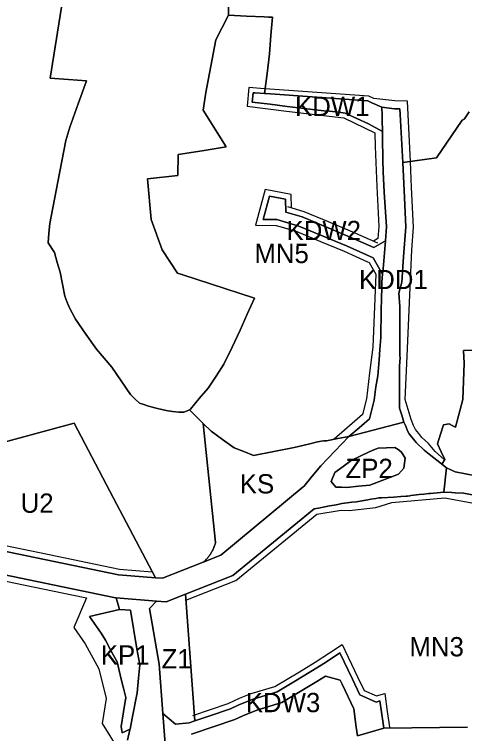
# Model space of a CAD drawing. Extents: x 7439486 to 7443435, y 5551288 to 5554556.
# Drawn here: x 7441851.7 to 7442085.2, y 5553243.9 to 5553616.6 of the extents above; entities that cross this region are included whole.
import ezdxf

# ---------------------------------------------------------------- set-up
doc = ezdxf.new("R2010")
doc.units = 0
for name, color, linetype in [('linie_rozgraniczajace', 7, 'Continuous'), ('linie_zabudowy_nieprzekraczalne', 7, 'Continuous'), ('oznaczenia_przeznaczen', 7, 'Continuous')]:
    doc.layers.add(name, color=color, linetype=linetype)

msp = doc.modelspace()

# ---------------------------------------------------------------- linework, layer by layer
at = {"layer": 'linie_rozgraniczajace'}
for points in [[(7441962.75, 5553632.44), (7441962.74, 5553616.11), (7441959.49, 5553609.73), (7441956.24, 5553603.34), (7441950.99, 5553576.02), (7441949.63, 5553566.86), (7441961.61, 5553547.92), (7441949.1, 5553545.9), (7441936.59, 5553543.88), (7441936.53, 5553533.08), (7441920.77, 5553531.3), (7441922.7, 5553510.32), (7441928.27, 5553494.51), (7441936.24, 5553482.52), (7441938.5, 5553481.78), (7441976.24, 5553469.44), (7441972.5, 5553461.19), (7441968.76, 5553452.94), (7441964.58, 5553444.11), (7441960.4, 5553435.27), (7441956.27, 5553429.09), (7441952.13, 5553422.91), (7441947.59, 5553417.49), (7441943.06, 5553412.07), (7441942.78, 5553411.84), (7441942.49, 5553411.61), (7441941, 5553411.04), (7441939.51, 5553410.48), (7441938.2, 5553410.46), (7441936.89, 5553410.43), (7441933.65, 5553410.86), (7441930.41, 5553411.3), (7441925.85, 5553412.42), (7441921.3, 5553413.55), (7441918.9, 5553414.35), (7441916.5, 5553415.15), (7441914.23, 5553417.4), (7441911.97, 5553419.64), (7441907.06, 5553426.72), (7441902.15, 5553433.79), (7441898.19, 5553438.45), (7441894.23, 5553443.11), (7441888.76, 5553450.84), (7441883.29, 5553458.57)], [(7442087.62, 5553566.03), (7442085.21, 5553562.48), (7442084.62, 5553562.08), (7442084.03, 5553561.67), (7442070.63, 5553542.14), (7442053.16, 5553539.76), (7442051.83, 5553564.65), (7442051.71, 5553567.66), (7442048.83, 5553567.69), (7442042.23, 5553568.53), (7442037.14, 5553570.76), (7442035.02, 5553571.68), (7441982.1, 5553575.51), (7441981.44, 5553575.5), (7441982.72, 5553585.84), (7441984, 5553596.18), (7441984.78, 5553605.62), (7441985.56, 5553615.05), (7441983.44, 5553615.15), (7441981.32, 5553615.25), (7441972.03, 5553615.68), (7441962.74, 5553616.11), (7441962.75, 5553632.44)], [(7441883.29, 5553458.57), (7441880.04, 5553464.85), (7441878.91, 5553467.7), (7441877.78, 5553470.56), (7441876.61, 5553476.73), (7441875.44, 5553482.9), (7441873.94, 5553488), (7441872.43, 5553493.11), (7441869.15, 5553498.19), (7441869.56, 5553503.21), (7441869.97, 5553508.24), (7441874.19, 5553529.73), (7441878.41, 5553551.23), (7441880.51, 5553558.15), (7441884.77, 5553570.17), (7441889.02, 5553582.18), (7441879.67, 5553582.82), (7441870.31, 5553583.46), (7441877.29, 5553628.08)], [(7441877.29, 5553628.08), (7441870.31, 5553583.46), (7441879.67, 5553582.82), (7441889.02, 5553582.18), (7441884.77, 5553570.17), (7441880.51, 5553558.15), (7441878.41, 5553551.23), (7441874.19, 5553529.73), (7441869.97, 5553508.24), (7441869.56, 5553503.21), (7441869.15, 5553498.19), (7441872.43, 5553493.11), (7441873.94, 5553488), (7441875.44, 5553482.9), (7441876.61, 5553476.73), (7441877.78, 5553470.56), (7441878.91, 5553467.7), (7441880.04, 5553464.85), (7441883.29, 5553458.57), (7441888.76, 5553450.84), (7441894.23, 5553443.11), (7441898.19, 5553438.45), (7441902.15, 5553433.79), (7441907.06, 5553426.72), (7441911.97, 5553419.64), (7441914.23, 5553417.4), (7441916.5, 5553415.15), (7441918.9, 5553414.35), (7441921.3, 5553413.55), (7441925.85, 5553412.42), (7441930.41, 5553411.3), (7441933.65, 5553410.86), (7441936.89, 5553410.43), (7441938.2, 5553410.46), (7441939.51, 5553410.48), (7441941, 5553411.04), (7441942.49, 5553411.61), (7441948.12, 5553406.08), (7441949.66, 5553404.57), (7441956, 5553342.87), (7441955.99, 5553342.81), (7441955.92, 5553342.54), (7441955.84, 5553342.27), (7441955.76, 5553342), (7441955.67, 5553341.73), (7441955.58, 5553341.46), (7441955.49, 5553341.19), (7441955.39, 5553340.93), (7441955.29, 5553340.66), (7441955.19, 5553340.4), (7441955.08, 5553340.14), (7441954.97, 5553339.88), (7441954.86, 5553339.62), (7441954.74, 5553339.36), (7441954.61, 5553339.11), (7441954.49, 5553338.85), (7441954.36, 5553338.6), (7441954.23, 5553338.35), (7441954.09, 5553338.1), (7441953.95, 5553337.86), (7441953.81, 5553337.61), (7441953.66, 5553337.37), (7441953.51, 5553337.13), (7441953.36, 5553336.9), (7441953.2, 5553336.66), (7441953.04, 5553336.43), (7441952.88, 5553336.2), (7441952.71, 5553335.97), (7441952.54, 5553335.74), (7441952.37, 5553335.52), (7441952.19, 5553335.3), (7441952.01, 5553335.08), (7441951.83, 5553334.86), (7441951.64, 5553334.65), (7441951.45, 5553334.44), (7441951.26, 5553334.23), (7441951.07, 5553334.03), (7441950.87, 5553333.82), (7441950.67, 5553333.62), (7441950.47, 5553333.43)], [(7441950.47, 5553333.43), (7441950.26, 5553333.23), (7441950.05, 5553333.04), (7441949.84, 5553332.85), (7441949.63, 5553332.67), (7441928.52, 5553324.38), (7441924.88, 5553324.65), (7441903.12, 5553365.93), (7441882.64, 5553404.78), (7441837.94, 5553392.64), (7441797.85, 5553381.74), (7441779.89, 5553399.7), (7441772.37, 5553423.56), (7441763.1, 5553465.1), (7441762.38, 5553469.23), (7441761.15, 5553476.2), (7441760.08, 5553479.21), (7441754.84, 5553512.36), (7441748.26, 5553539.53), (7441742.45, 5553554.52), (7441720.8, 5553590.65), (7441712.24, 5553615.6)], [(7442095.79, 5553442.72), (7442084.64, 5553442.43), (7442084.84, 5553439.13), (7442085.04, 5553435.82), (7442084.71, 5553426.45), (7442084.38, 5553417.07), (7442082.73, 5553411.05), (7442080.55, 5553402.75), (7442078.85, 5553403.53), (7442077.15, 5553404.32), (7442074.34, 5553403.88), (7442072.78, 5553398.98), (7442071.22, 5553394.08), (7442073.09, 5553389.97), (7442074.96, 5553385.86), (7442073.48, 5553383.49), (7442072.38, 5553384.39), (7442067.78, 5553387.97), (7442064.3, 5553390.67), (7442060.1, 5553394.64), (7442056.47, 5553399.26), (7442055.81, 5553400.37), (7442054.5, 5553403.48), (7442053.72, 5553405.32), (7442052.62, 5553408.93), (7442051.52, 5553412.54), (7442051.5, 5553415.07), (7442051.48, 5553417.6), (7442051.5, 5553425.9), (7442051.5, 5553429.07), (7442051.51, 5553434.19), (7442051.63, 5553436.52), (7442051.76, 5553438.85), (7442051.7, 5553439.45), (7442051.64, 5553465.17), (7442051.06, 5553472.18), (7442052.63, 5553477.77), (7442053.53, 5553490.87), (7442054.72, 5553506.39), (7442053.93, 5553525.25), (7442053.16, 5553539.76), (7442070.63, 5553542.14), (7442084.03, 5553561.67), (7442084.62, 5553562.08), (7442085.21, 5553562.48), (7442087.62, 5553566.03)], [(7442082.73, 5553411.05), (7442084.38, 5553417.07), (7442084.71, 5553426.45), (7442085.04, 5553435.82), (7442084.84, 5553439.13), (7442084.64, 5553442.43), (7442095.79, 5553442.72)], [(7442112.53, 5553373.36), (7442080.38, 5553379.45), (7442075.77, 5553381.65), (7442073.48, 5553383.49), (7442074.96, 5553385.86), (7442073.09, 5553389.97), (7442071.22, 5553394.08), (7442072.78, 5553398.98), (7442074.34, 5553403.88), (7442077.15, 5553404.32), (7442078.85, 5553403.53), (7442080.55, 5553402.75), (7442082.73, 5553411.05)], [(7441824.52, 5553342.9), (7441905.74, 5553326.1), (7441924.88, 5553324.65), (7441928.52, 5553324.38), (7441949.63, 5553332.67), (7441958.83, 5553336.28), (7442001.52, 5553371.75), (7442001.79, 5553371.99), (7442006.18, 5553377.33), (7442010.57, 5553382.67), (7442017.91, 5553390.22), (7442025.24, 5553397.77), (7442053.72, 5553405.32), (7442054.5, 5553403.48), (7442055.81, 5553400.37), (7442056.47, 5553399.26), (7442060.1, 5553394.64), (7442064.3, 5553390.67), (7442067.78, 5553387.97), (7442072.38, 5553384.39), (7442073.48, 5553383.49), (7442075.77, 5553381.65), (7442074.52, 5553369.06), (7442067.61, 5553368.34), (7442066.62, 5553368.23), (7442064.13, 5553367.97), (7442061.65, 5553367.71), (7442058.83, 5553367.42), (7442057.26, 5553367.2), (7442056.85, 5553367.14), (7442055.69, 5553366.98), (7442054.87, 5553366.87), (7442052.2, 5553366.7), (7442048.46, 5553366.47), (7442042.04, 5553366.06), (7442040.73, 5553366.03), (7442039.25, 5553365.77), (7442036.6, 5553365.3), (7442034.97, 5553365.01), (7442030.05, 5553364.13), (7442029.21, 5553363.98), (7442026.77, 5553363.73), (7442024.33, 5553363.49), (7442022.97, 5553363.26), (7442021.61, 5553363.03), (7442020.11, 5553362.75), (7442018.61, 5553362.47), (7442017.62, 5553362.28), (7442015.17, 5553361.82), (7442012.71, 5553361.36), (7442009.38, 5553360.73), (7442007.23, 5553360.33), (7441964.97, 5553325.8), (7441940.46, 5553316.18), (7441930.35, 5553312.2), (7441925.47, 5553312.57), (7441904.54, 5553314.16), (7441904.06, 5553314.19), (7441823.17, 5553330.92)], [(7442074.52, 5553369.06), (7442075.77, 5553381.65), (7442080.38, 5553379.45), (7442112.53, 5553373.36)], [(7442086.81, 5553247.26), (7442043.26, 5553246.77), (7442042.92, 5553249.2), (7442041.28, 5553260.8), (7442039.37, 5553260.22), (7442030.91, 5553263.95), (7442027.04, 5553272.06), (7442020.54, 5553285.65), (7442013.02, 5553280.81), (7442005.49, 5553275.98), (7441996.71, 5553270.74), (7441987.93, 5553265.51), (7441981.71, 5553263.64), (7441975.49, 5553261.76), (7441971.59, 5553260.19), (7441967.69, 5553258.62), (7441963.71, 5553256.74), (7441953.02, 5553253.12), (7441945.2, 5553250.47), (7441940.46, 5553316.18), (7441964.97, 5553325.8), (7442007.23, 5553360.33), (7442009.38, 5553360.73), (7442012.71, 5553361.36), (7442015.17, 5553361.82), (7442017.62, 5553362.28), (7442018.61, 5553362.47), (7442020.11, 5553362.75), (7442021.61, 5553363.03), (7442022.97, 5553363.26), (7442024.33, 5553363.49), (7442026.77, 5553363.73), (7442029.21, 5553363.98), (7442030.05, 5553364.13), (7442034.97, 5553365.01), (7442036.6, 5553365.3), (7442039.25, 5553365.77), (7442040.73, 5553366.03), (7442042.04, 5553366.06), (7442048.46, 5553366.47), (7442052.2, 5553366.7), (7442054.87, 5553366.87), (7442055.69, 5553366.98), (7442056.85, 5553367.14), (7442057.26, 5553367.2), (7442058.83, 5553367.42), (7442061.65, 5553367.71), (7442064.13, 5553367.97), (7442066.62, 5553368.23), (7442067.61, 5553368.34), (7442074.52, 5553369.06), (7442078.57, 5553368.82), (7442080.26, 5553368.71), (7442084.74, 5553368.45), (7442109.65, 5553363.73)], [(7442109.65, 5553363.73), (7442084.74, 5553368.45), (7442080.26, 5553368.71), (7442078.57, 5553368.82), (7442074.52, 5553369.06)], [(7441625.43, 5553307.24), (7441692.79, 5553320.41), (7441753.67, 5553331.12), (7441780.26, 5553331.8), (7441823.17, 5553330.92), (7441904.06, 5553314.19), (7441904.54, 5553314.16), (7441906.16, 5553308.16), (7441890.69, 5553304.55), (7441896.75, 5553295.85), (7441898.88, 5553292.27), (7441901.92, 5553286.67), (7441904.97, 5553281.08), (7441907.04, 5553272.17), (7441908.22, 5553267.37), (7441909.4, 5553262.57), (7441908.24, 5553255.09), (7441907.09, 5553247.61), (7441907.63, 5553244.24), (7441911.71, 5553246.12), (7441911.64, 5553245.76), (7441910.26, 5553240.49)], [(7441910.26, 5553240.49), (7441911.64, 5553245.76), (7441911.71, 5553246.12), (7441912.81, 5553251.84), (7441915.34, 5553264.93), (7441915.69, 5553268.76), (7441916.05, 5553272.59), (7441916.37, 5553276.03), (7441916.69, 5553279.46), (7441915.27, 5553287.82), (7441911.85, 5553307.89), (7441906.16, 5553308.16), (7441904.54, 5553314.16), (7441925.47, 5553312.57), (7441921.84, 5553308.78), (7441926.77, 5553279.84), (7441928.74, 5553254.3), (7441930.13, 5553236.35)], [(7441930.13, 5553236.35), (7441928.74, 5553254.3), (7441935.18, 5553248.85), (7441942.33, 5553249.5), (7441945.2, 5553250.47), (7441953.02, 5553253.12), (7441963.71, 5553256.74), (7441967.69, 5553258.62), (7441971.59, 5553260.19), (7441975.49, 5553261.76), (7441981.71, 5553263.64), (7441987.93, 5553265.51), (7441996.71, 5553270.74), (7442005.49, 5553275.98), (7442013.02, 5553280.81), (7442020.54, 5553285.65), (7442027.04, 5553272.06), (7442030.91, 5553263.95), (7442039.37, 5553260.22), (7442041.28, 5553260.8), (7442042.92, 5553249.2), (7442043.26, 5553246.77), (7442029.7, 5553242.69), (7442029.06, 5553247.24), (7442027.72, 5553256.71), (7442021.63, 5553269.47), (7442020.61, 5553271.6), (7442013.07, 5553273.71), (7442008.65, 5553270.88), (7441990.36, 5553259.98), (7441977.48, 5553256.1), (7441970.1, 5553253.13), (7441965.97, 5553251.17), (7441943.58, 5553243.59)], [(7441943.58, 5553243.59), (7441965.97, 5553251.17), (7441970.1, 5553253.13), (7441977.48, 5553256.1), (7441990.36, 5553259.98), (7442008.65, 5553270.88), (7442013.07, 5553273.71), (7442020.61, 5553271.6), (7442021.63, 5553269.47), (7442027.72, 5553256.71), (7442029.06, 5553247.24), (7442029.7, 5553242.69), (7442043.26, 5553246.77), (7442086.81, 5553247.26)]]:
    msp.add_lwpolyline(points, dxfattribs=at)
for points in [[(7441920.77, 5553531.3), (7441936.53, 5553533.08), (7441936.59, 5553543.88), (7441949.1, 5553545.9), (7441961.61, 5553547.92), (7441949.63, 5553566.86), (7441950.99, 5553576.02), (7441956.24, 5553603.34), (7441959.49, 5553609.73), (7441962.74, 5553616.11), (7441972.03, 5553615.68), (7441981.32, 5553615.25), (7441983.44, 5553615.15), (7441985.56, 5553615.05), (7441984.78, 5553605.62), (7441984, 5553596.18), (7441982.72, 5553585.84), (7441981.44, 5553575.5), (7441976.46, 5553575.82), (7441975.59, 5553575.91), (7441975.1, 5553571.11), (7441984.42, 5553569.95), (7441993.18, 5553568.86), (7442001.94, 5553567.77), (7442012.22, 5553566.59), (7442015.15, 5553566.38), (7442019.98, 5553565.83), (7442023.24, 5553565.44), (7442035.33, 5553559.79), (7442042.59, 5553555.94), (7442042.6, 5553555.44), (7442042.7, 5553550.44), (7442042.72, 5553549.44), (7442042.82, 5553544.44), (7442042.89, 5553540.94), (7442043.01, 5553535.05), (7442043.58, 5553524.38), (7442044.7, 5553506.54), (7442044.12, 5553499.29), (7442038.16, 5553495.71), (7442025.89, 5553501.18), (7442000.88, 5553511.57), (7441992.42, 5553514.08), (7441992.31, 5553520.73), (7441983.95, 5553522.36), (7441980.72, 5553510.25), (7441987.88, 5553510.21), (7441999.21, 5553506.85), (7442023.91, 5553496.59), (7442037.76, 5553490.41), (7442042.7, 5553481.97), (7442042.34, 5553478.01), (7442042.25, 5553475.22), (7442042.06, 5553469.22), (7442041.87, 5553463.22), (7442041.71, 5553449.07), (7442041.31, 5553442.93), (7442040.88, 5553437.53), (7442040.23, 5553429.26), (7442039.12, 5553423.62), (7442038.27, 5553416.59), (7442035.88, 5553406.98), (7442030.56, 5553402.37), (7442025.24, 5553397.77), (7442019.38, 5553396.71), (7442013.52, 5553395.64), (7442012.15, 5553395.53), (7442010.78, 5553395.42), (7442008.22, 5553394.84), (7442005.67, 5553394.25), (7442001.24, 5553393.23), (7441996.81, 5553392.21), (7441986.29, 5553390.14), (7441975.77, 5553388.06), (7441970.72, 5553389.99), (7441965.67, 5553391.93), (7441959.71, 5553396.25), (7441953.75, 5553400.56), (7441949.66, 5553404.57), (7441948.12, 5553406.08), (7441942.49, 5553411.61), (7441942.78, 5553411.84), (7441943.06, 5553412.07), (7441947.59, 5553417.49), (7441952.13, 5553422.91), (7441956.27, 5553429.09), (7441960.4, 5553435.27), (7441964.58, 5553444.11), (7441968.76, 5553452.94), (7441972.5, 5553461.19), (7441976.24, 5553469.44), (7441938.5, 5553481.78), (7441936.24, 5553482.52), (7441928.27, 5553494.51), (7441922.7, 5553510.32)], [(7441975.1, 5553571.11), (7441975.59, 5553575.91), (7441976.46, 5553575.82), (7441981.44, 5553575.5), (7441982.1, 5553575.51), (7442035.02, 5553571.68), (7442037.14, 5553570.76), (7442042.23, 5553568.53), (7442042.4, 5553564.27), (7442042.45, 5553563.12), (7442042.48, 5553561.44), (7442042.58, 5553556.44), (7442042.59, 5553555.94), (7442035.33, 5553559.79), (7442023.24, 5553565.44), (7442019.98, 5553565.83), (7442015.15, 5553566.38), (7442012.22, 5553566.59), (7442001.94, 5553567.77), (7441993.18, 5553568.86), (7441984.42, 5553569.95)], [(7442025.24, 5553397.77), (7442030.56, 5553402.37), (7442035.88, 5553406.98), (7442038.27, 5553416.59), (7442039.12, 5553423.62), (7442040.23, 5553429.26), (7442040.88, 5553437.53), (7442041.31, 5553442.93), (7442041.71, 5553449.07), (7442041.87, 5553463.22), (7442042.06, 5553469.22), (7442042.25, 5553475.22), (7442042.34, 5553478.01), (7442042.7, 5553481.97), (7442042.96, 5553484.79), (7442044.12, 5553499.29), (7442044.7, 5553506.54), (7442043.58, 5553524.38), (7442043.01, 5553535.05), (7442042.89, 5553540.94), (7442042.82, 5553544.44), (7442042.72, 5553549.44), (7442042.7, 5553550.44), (7442042.6, 5553555.44), (7442042.59, 5553555.94), (7442042.58, 5553556.44), (7442042.48, 5553561.44), (7442042.45, 5553563.12), (7442042.4, 5553564.27), (7442042.23, 5553568.53), (7442048.83, 5553567.69), (7442051.71, 5553567.66), (7442051.83, 5553564.65), (7442053.16, 5553539.76), (7442053.93, 5553525.25), (7442054.72, 5553506.39), (7442053.53, 5553490.87), (7442052.63, 5553477.77), (7442051.06, 5553472.18), (7442051.64, 5553465.17), (7442051.7, 5553439.45), (7442051.76, 5553438.85), (7442051.63, 5553436.52), (7442051.51, 5553434.19), (7442051.5, 5553429.07), (7442051.5, 5553425.9), (7442051.48, 5553417.6), (7442051.5, 5553415.07), (7442051.52, 5553412.54), (7442052.62, 5553408.93), (7442053.72, 5553405.32)], [(7441980.72, 5553510.25), (7441983.95, 5553522.36), (7441992.31, 5553520.73), (7441992.42, 5553514.08), (7442000.88, 5553511.57), (7442025.89, 5553501.18), (7442038.16, 5553495.71), (7442044.12, 5553499.29), (7442042.96, 5553484.79), (7442042.7, 5553481.97), (7442037.76, 5553490.41), (7442023.91, 5553496.59), (7441999.21, 5553506.85), (7441987.88, 5553510.21)], [(7441797.85, 5553381.74), (7441837.94, 5553392.64), (7441882.64, 5553404.78), (7441903.12, 5553365.93), (7441924.88, 5553324.65), (7441905.74, 5553326.1), (7441824.52, 5553342.9), (7441819.72, 5553342.99), (7441814.41, 5553348.91), (7441814.82, 5553364.77)], [(7441949.63, 5553332.67), (7441949.84, 5553332.85), (7441950.05, 5553333.04), (7441950.26, 5553333.23), (7441950.47, 5553333.43), (7441950.67, 5553333.62), (7441950.87, 5553333.82), (7441951.07, 5553334.03), (7441951.26, 5553334.23), (7441951.45, 5553334.44), (7441951.64, 5553334.65), (7441951.83, 5553334.86), (7441952.01, 5553335.08), (7441952.19, 5553335.3), (7441952.37, 5553335.52), (7441952.54, 5553335.74), (7441952.71, 5553335.97), (7441952.88, 5553336.2), (7441953.04, 5553336.43), (7441953.2, 5553336.66), (7441953.36, 5553336.9), (7441953.51, 5553337.13), (7441953.66, 5553337.37), (7441953.81, 5553337.61), (7441953.95, 5553337.86), (7441954.09, 5553338.1), (7441954.23, 5553338.35), (7441954.36, 5553338.6), (7441954.49, 5553338.85), (7441954.61, 5553339.11), (7441954.74, 5553339.36), (7441954.86, 5553339.62), (7441954.97, 5553339.88), (7441955.08, 5553340.14), (7441955.19, 5553340.4), (7441955.29, 5553340.66), (7441955.39, 5553340.93), (7441955.49, 5553341.19), (7441955.58, 5553341.46), (7441955.67, 5553341.73), (7441955.76, 5553342), (7441955.84, 5553342.27), (7441955.92, 5553342.54), (7441955.99, 5553342.81), (7441956, 5553342.87), (7441949.66, 5553404.57), (7441953.75, 5553400.56), (7441959.71, 5553396.25), (7441965.67, 5553391.93), (7441970.72, 5553389.99), (7441975.77, 5553388.06), (7441986.29, 5553390.14), (7441996.81, 5553392.21), (7442001.24, 5553393.23), (7442005.67, 5553394.25), (7442008.22, 5553394.84), (7442010.78, 5553395.42), (7442012.15, 5553395.53), (7442013.52, 5553395.64), (7442019.38, 5553396.71), (7442025.24, 5553397.77), (7442017.91, 5553390.22), (7442010.57, 5553382.67), (7442006.18, 5553377.33), (7442001.79, 5553371.99), (7442001.52, 5553371.75), (7441958.83, 5553336.28)], [(7442016.09, 5553374.48), (7442017.99, 5553379.09), (7442022.21, 5553382.22), (7442026.44, 5553385.34), (7442031.08, 5553387.57), (7442035.72, 5553389.81), (7442038.08, 5553390.84), (7442040.43, 5553391.86), (7442044.74, 5553391.99), (7442049.05, 5553392.11), (7442050.7, 5553391.03), (7442052.35, 5553389.95), (7442053.35, 5553388.28), (7442054.35, 5553386.6), (7442054.03, 5553384.03), (7442053.71, 5553381.46), (7442052.35, 5553379.88), (7442050.99, 5553378.29), (7442036.02, 5553372.69), (7442030.11, 5553372.08), (7442024.2, 5553371.48), (7442021.33, 5553371.49), (7442018.46, 5553371.5)], [(7442016.09, 5553374.48), (7442018.46, 5553371.5), (7442021.33, 5553371.49), (7442024.2, 5553371.48), (7442030.11, 5553372.08), (7442036.02, 5553372.69), (7442050.99, 5553378.29), (7442052.35, 5553379.88), (7442053.71, 5553381.46), (7442054.03, 5553384.03), (7442054.35, 5553386.6), (7442053.35, 5553388.28), (7442052.35, 5553389.95), (7442050.7, 5553391.03), (7442049.05, 5553392.11), (7442044.74, 5553391.99), (7442040.43, 5553391.86), (7442038.08, 5553390.84), (7442035.72, 5553389.81), (7442031.08, 5553387.57), (7442026.44, 5553385.34), (7442022.21, 5553382.22), (7442017.99, 5553379.09)], [(7441921.84, 5553308.78), (7441925.47, 5553312.57), (7441930.35, 5553312.2), (7441940.46, 5553316.18), (7441945.2, 5553250.47), (7441942.33, 5553249.5), (7441935.18, 5553248.85), (7441928.74, 5553254.3), (7441926.77, 5553279.84)], [(7441890.69, 5553304.55), (7441906.16, 5553308.16), (7441911.85, 5553307.89), (7441915.27, 5553287.82), (7441916.69, 5553279.46), (7441916.37, 5553276.03), (7441916.05, 5553272.59), (7441915.69, 5553268.76), (7441915.34, 5553264.93), (7441912.81, 5553251.84), (7441911.71, 5553246.12), (7441907.63, 5553244.24), (7441907.09, 5553247.61), (7441908.24, 5553255.09), (7441909.4, 5553262.57), (7441908.22, 5553267.37), (7441907.04, 5553272.17), (7441904.97, 5553281.08), (7441901.92, 5553286.67), (7441898.88, 5553292.27), (7441896.75, 5553295.85)]]:
    msp.add_lwpolyline(points, close=True, dxfattribs=at)
at = {"layer": 'linie_zabudowy_nieprzekraczalne'}
for points in [[(7442074.88, 5553385.73), (7442069.9, 5553390.05), (7442068.17, 5553392.1), (7442066.44, 5553394.15), (7442064.75, 5553395.75), (7442063.07, 5553397.34), (7442061.42, 5553399.44), (7442059.78, 5553401.53), (7442058.78, 5553403.61), (7442057.48, 5553406.68), (7442056.96, 5553408.39), (7442056.45, 5553410.09), (7442055.39, 5553413.58), (7442054.33, 5553417.07), (7442054.86, 5553428.24), (7442055.39, 5553439.45), (7442056.61, 5553467.19), (7442057.81, 5553494.63), (7442058.72, 5553506.32), (7442057.76, 5553526.84), (7442057.13, 5553540.3), (7442055.55, 5553571.62), (7442049.1, 5553571.69), (7442038.14, 5553573.05), (7442035.63, 5553574.15), (7441984.25, 5553577.86), (7441981.49, 5553578), (7441973.36, 5553578.64), (7441972.36, 5553568.94), (7441992.88, 5553566.38), (7442011.98, 5553564.1), (7442022.54, 5553563), (7442038.6, 5553555.23), (7442038.75, 5553548.15), (7442039.72, 5553527.38), (7442040.69, 5553506.6), (7442040.21, 5553500.44), (7442037.96, 5553499.08)], [(7441995.38, 5553516.33), (7441995.27, 5553523.2), (7441981.78, 5553525.84), (7441976.82, 5553507.27), (7441987.44, 5553507.21), (7441990.14, 5553506.41), (7441998.2, 5553504.02), (7442010.46, 5553498.93), (7442022.72, 5553493.84), (7442034.9, 5553488.4), (7442035.65, 5553488.07), (7442039.24, 5553481.94), (7442037.58, 5553444.05), (7442035.96, 5553430.78), (7442034.33, 5553417.32), (7442032.3, 5553409.17), (7442017.51, 5553396.37)], [(7441993.27, 5553516.95), (7442001.89, 5553514.4), (7442014.48, 5553509.17), (7442027.07, 5553503.94), (7442040.03, 5553498.16)], [(7441802.29, 5553382.95), (7441818.86, 5553366.39), (7441818.45, 5553350.4), (7441822.45, 5553345.94), (7441824.86, 5553345.89), (7441865.51, 5553337.48), (7441906.16, 5553329.08), (7441923.14, 5553327.79)], [(7441940.69, 5553313.04), (7441966.5, 5553323.18), (7442008.54, 5553357.53), (7442021.16, 5553359.63), (7442025.36, 5553359.56), (7442039.13, 5553361.06), (7442047.5, 5553363.58), (7442074.98, 5553366.05), (7442108.55, 5553359.86)], [(7441626.02, 5553304.3), (7441674.9, 5553313.55), (7441723.77, 5553322.81), (7441753.97, 5553328.13), (7441780.26, 5553328.8), (7441822.83, 5553327.93), (7441881.43, 5553315.81), (7441889.04, 5553314.24), (7441882.48, 5553298.83), (7441888.34, 5553290.43), (7441895.54, 5553277.49), (7441899.21, 5553262.12), (7441897.21, 5553249.13), (7441906.07, 5553234.99)], [(7441944.24, 5553253.31), (7441962.61, 5553259.54), (7441968.46, 5553262.17), (7441974.49, 5553264.6), (7441986.71, 5553268.28), (7441999.55, 5553275.93), (7442007.66, 5553280.94), (7442015.16, 5553285.75), (7442021.78, 5553290.01), (7442029.75, 5553273.35), (7442033.14, 5553266.24), (7442039.56, 5553263.41), (7442043.77, 5553264.68), (7442045.07, 5553255.42), (7442045.89, 5553249.61), (7442046.23, 5553247.19)]]:
    msp.add_lwpolyline(points, dxfattribs=at)

# ---------------------------------------------------------------- texts
at = {"layer": 'oznaczenia_przeznaczen'}
for s, p in [('KDW1', (7441997.26, 5553563.92)), ('KDW2', (7441992.85, 5553499.57)), ('MN5', (7441976.18, 5553487.68)), ('KDD1', (7442030.45, 5553474.18)), ('ZP2', (7442023.45, 5553376.3)), ('KS', (7441968.6, 5553368.31)), ('U2', (7441854.92, 5553358.31)), ('MN3', (7442056.63, 5553283.9)), ('KP1', (7441896.51, 5553279.62)), ('Z1', (7441928.01, 5553277.67)), ('KDW3', (7441971.74, 5553254.98))]:
    msp.add_text(s, height=10, dxfattribs=at).set_placement(p)

doc.saveas('drawing.dxf')
